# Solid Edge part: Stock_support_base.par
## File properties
Accuracy: 0.99
Title: Stock Support Base
Author: Abhinav Rai
Template: Normal.par
Last saved by: TIET
Revision: 22
Application: Solid Edge
Material: aluminum
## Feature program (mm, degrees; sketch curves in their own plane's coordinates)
sketch for "unnamed RevolvedProtrusion 1" plane through (0, 0, 0) normal (0, -1, 0) x-axis (1, 0, 0)
  line (0, 29.2468) -> (71.7103, 29.2468)
  line (71.7103, 29.2468) -> (71.7103, 19.7218)
  line (71.7103, 19.7218) -> (165.1, -256.5032)
  line (165.1, -256.5032) -> (215.9, -256.5032)
  line (215.9, -256.5032) -> (215.9, -281.9032)
  line (215.9, -281.9032) -> (156.9298, -281.9032)
  line (156.9298, -281.9032) -> (85.052, -69.3053)
  arc centre (73.021, -73.3729) radius 12.7 from (60.325, -73.0538) to (85.052, -69.3053) cw
  line (60.325, -73.0538) -> (57.15, -199.3532)
  line (57.15, -199.3532) -> (0, -199.3532)
  line (0, 29.2468) -> (0, -199.3532)
revolve "unnamed RevolvedProtrusion 1" add full turn 360 deg
sketch for "unnamed Hole 1" plane through (0, 0, 29.2468) normal (0, 0, 1) x-axis (1, 0, 0)
  hole centre (0, 0) bore radius 38.1
hole "unnamed Hole 1" through
sketch for "ExtrudedProtrusion_2" plane through (0, 0, -256.5032) normal (0, 0, 1) x-axis (0, 1, 0)
  arc centre (0, -119.2664) radius 41.0756 from (-18.7686, -155.8034) to (18.7686, -155.8034) ccw
  line (-18.7686, -197.1314) -> (-18.7686, -155.8034)
  arc centre (0, -197.1314) radius 18.7686 from (18.7686, -197.1314) to (-18.7686, -197.1314) cw
  line (18.7686, -197.1314) -> (18.7686, -155.8034)
extrude "ExtrudedProtrusion_2" add finite 12.7 along +normal
sketch for "unnamed Hole 2" plane through (187.8036, 0, -243.8032) normal (0, 0, 1) x-axis (1, 0, 0)
hole "unnamed Hole 2" through
fillet "Round_4" radius 3.175
pattern "unnamed Pattern 1" of "ExtrudedProtrusion_2", "unnamed Hole 2", "Round_4"
pattern "unnamed Pattern 2"
sketch for "ExtrudedProtrusion_3" plane through (0, -134.62, 0) normal (0, -1, 0) x-axis (1, 0, 0)
  circle centre (0, -2.5032) radius 19.05
extrude "ExtrudedProtrusion_3" add  Plane_Distance = 134.62 mm
adv blend "unnamed AdvBlend 1"
sketch for "ExtrudedProtrusion_4" plane through (0, -134.62, -2.5032) normal (0, -1, 0) x-axis (1, 0, 0)
  circle centre (0, -3.81) radius 22.225
extrude "ExtrudedProtrusion_4" add finite 9.525 along +normal
mirror "unnamed Mirror 1" of "ExtrudedProtrusion_4", "unnamed AdvBlend 1", "ExtrudedProtrusion_3" about plane through (0, 0, 0) normal (0, -1, 0)
extrude "unnamed Protrusion 1" add
adv blend "unnamed AdvBlend 2"
extrude "unnamed Protrusion 2" add finite 9.525
sketch for "ExtrudedProtrusion_7" plane through (104.775, 0, 0) normal (1, 0, 0) x-axis (0, 1, 0)
  circle centre (0, -167.6032) radius 19.05
extrude "ExtrudedProtrusion_7" add finite 41.275 along +normal  Plane_Distance = 104.775 mm
sketch for "unnamed Hole 3" plane through (146.05, 0, -167.6032) normal (1, 0, 0) x-axis (0, 1, 0)
  hole centre (0, 0) bore radius 7.9375
hole "unnamed Hole 3" through
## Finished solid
Body 1: solid body, 54 faces, 95 edges, 41 vertices.
  Faces by surface: plane 26, cylinder 19, torus 4, cone 3, blend 2
  Edges by curve: circle 57, intersection 20, line 18
Bounding box of the edges (mm; curved faces can reach further): 431.800 x 431.800 x 311.150, from (-215.9, -215.9, -281.9032) to (215.9, 215.9, 29.2468).
Cylindrical faces by radius (mm): R7.9375 x1, R11.1125 x3, R15.875 x3, R18.7686 x3, R19.05 x4, R22.225 x2, R38.1 x1, R71.7103 x1, R215.9 x1
Conical faces (half-angle, radius in mm at the cone's reference point): 1.44 deg R60.325 x1, 18.68 deg R71.7103 x1, 18.68 deg R156.9298 x1
Toroidal faces (ring radius, tube radius in mm): R73.021 r12.7 x1, R163.0843 r3.175 x3
Planar faces by outward normal: +x 1, +y 4, +z 10, -x 1, -y 4, -z 2, oblique 4
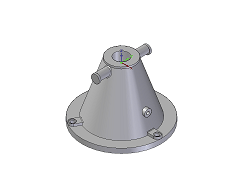
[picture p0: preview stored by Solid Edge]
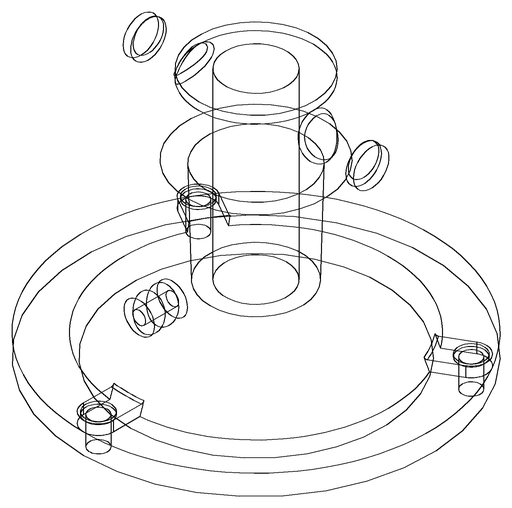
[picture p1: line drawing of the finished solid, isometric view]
